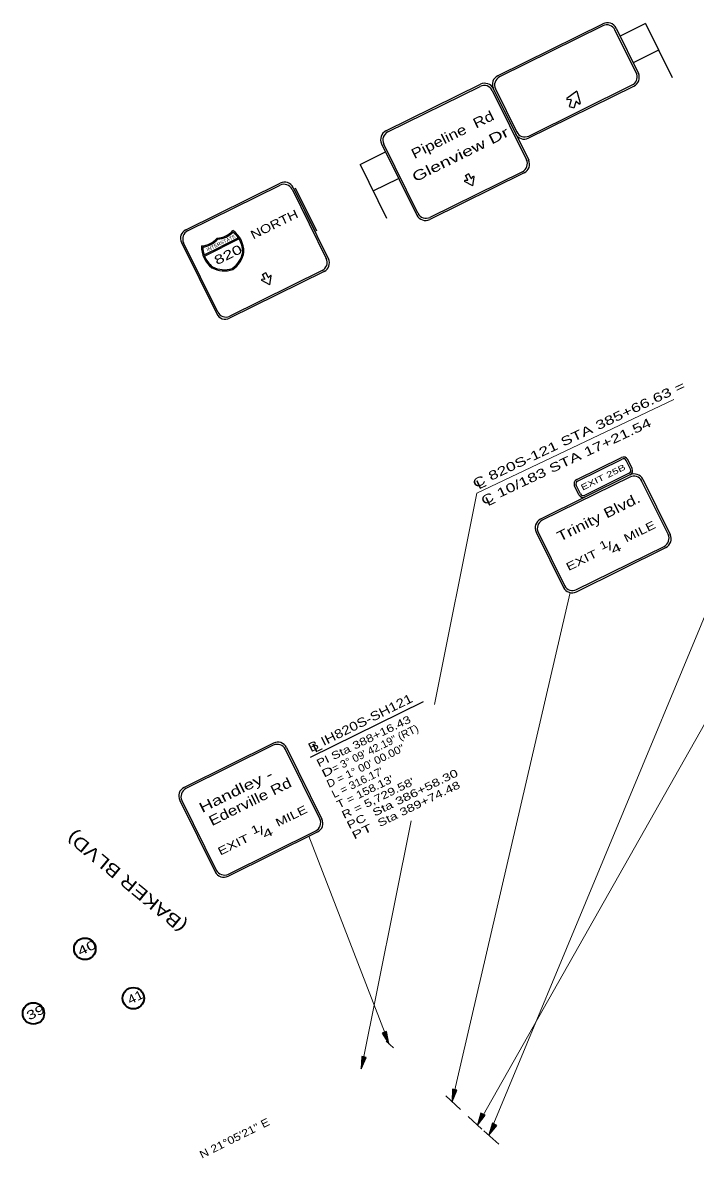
# Model space of a CAD drawing. Extents: x 2356431 to 2371438, y 6972864 to 6982525.
# Drawn here: x 2365913 to 2366966, y 6980043 to 6981822 of the extents above; entities that cross this region are included whole.
import ezdxf
from ezdxf.enums import TextEntityAlignment as Align

# ---------------------------------------------------------------- set-up
doc = ezdxf.new("R2010")
doc.units = 0
doc.header["$LTSCALE"] = 5.6
for name, color, linetype, lineweight in [('1', 7, 'Continuous', 25), ('13', 7, 'Continuous', 13), ('17', 7, 'Continuous', 35), ('28', 7, 'Continuous', 35), ('48', 7, 'Continuous', 25), ('61', 7, 'Continuous', 13)]:
    doc.layers.add(name, color=color, linetype=linetype, lineweight=lineweight)
doc.layers.add('25', color=7, linetype='Continuous')
doc.layers.add('33', color=7, linetype='Continuous')

msp = doc.modelspace()

# ---------------------------------------------------------------- hatches: boundary and pattern name
at = {"layer": '1'}
for points in [[(2366486.56, 6980222.747), (2366482.79, 6980241.916), (2366476.099, 6980239.246)], [(2366585.711, 6980131.985), (2366593.167, 6980150.043), (2366586.115, 6980151.517)], [(2366625.507, 6980094.921), (2366637.074, 6980110.661), (2366630.583, 6980113.784)], [(2366643.099, 6980079.535), (2366655.343, 6980094.757), (2366648.996, 6980098.16)]]:
    msp.add_hatch(color=256, dxfattribs=at).paths.add_polyline_path(points)
at = {"layer": '48'}
msp.add_hatch(color=256, dxfattribs=at).paths.add_polyline_path([(2366443.028, 6980183.363), (2366450.955, 6980201.225), (2366443.947, 6980202.876)])

# ---------------------------------------------------------------- linework, layer by layer
at = {"layer": '1'}
for p, q in [((2366822.168, 6981820.871), (2366656.942, 6981739.325)), ((2366821.727, 6981817.511), (2366659.872, 6981737.639)), ((2366888.321, 6981821.061), (2366848.562, 6981801.372)), ((2366888.321, 6981821.061), (2366930.054, 6981736.797)), ((2366874.917, 6981741.577), (2366840.613, 6981811.099)), ((2366842.31, 6981814.041), (2366877.397, 6981742.946)), ((2366908.913, 6981779.484), (2366869.153, 6981759.794)), ((2366481.942, 6981652.907), (2366630.021, 6981725.98)), ((2366484.869, 6981651.214), (2366629.585, 6981722.627)), ((2366648.42, 6981716.248), (2366701.973, 6981607.725)), ((2366650.101, 6981719.175), (2366705.488, 6981606.941)), ((2366650.101, 6981719.175), (2366684.907, 6981648.642)), ((2366653.469, 6981718.733), (2366686.91, 6981650.971)), ((2366704.924, 6981641.421), (2366870.141, 6981722.966)), ((2366705.635, 6981644.919), (2366867.652, 6981724.878)), ((2366780.897, 6981714.988), (2366765.399, 6981703.698)), ((2366780.897, 6981714.988), (2366786.306, 6981696.607)), ((2366771.515, 6981701.957), (2366765.978, 6981701.831)), ((2366772.181, 6981701.053), (2366768.834, 6981691.215)), ((2366779.329, 6981698.625), (2366775.995, 6981688.797)), ((2366780.379, 6981698.947), (2366784.722, 6981695.486)), ((2366768.834, 6981691.215), (2366772.414, 6981690.006)), ((2366775.995, 6981688.797), (2366772.414, 6981690.006)), ((2366475.143, 6981632.812), (2366530.353, 6981520.922)), ((2366532.043, 6981523.846), (2366478.48, 6981632.381)), ((2366441.311, 6981600.432), (2366481.125, 6981620.012)), ((2366441.311, 6981600.432), (2366482.812, 6981516.051)), ((2366698.515, 6981587.205), (2366550.438, 6981514.12)), ((2366695.596, 6981588.891), (2366550.879, 6981517.469)), ((2366168.323, 6981498.126), (2366316.402, 6981571.199)), ((2366461.788, 6981558.797), (2366501.602, 6981578.38)), ((2366617.788, 6981566.663), (2366605.165, 6981573.536)), ((2366609.552, 6981575.437), (2366605.418, 6981574.966)), ((2366606.491, 6981583.139), (2366609.031, 6981584.39)), ((2366609.941, 6981576.158), (2366606.491, 6981583.139)), ((2366611.579, 6981585.637), (2366609.031, 6981584.39)), ((2366615.033, 6981578.666), (2366611.579, 6981585.637)), ((2366615.859, 6981578.54), (2366618.718, 6981581.531)), ((2366617.788, 6981566.663), (2366620.002, 6981580.859)), ((2366171.25, 6981496.433), (2366315.966, 6981567.846)), ((2366334.801, 6981561.467), (2366388.354, 6981452.944)), ((2366336.482, 6981564.394), (2366391.869, 6981452.16)), ((2366336.482, 6981564.394), (2366371.288, 6981493.861)), ((2366339.85, 6981563.952), (2366373.291, 6981496.19)), ((2366250.828, 6981485.234), (2366223.926, 6981471.955)), ((2366251.833, 6981483.619), (2366224.765, 6981470.261)), ((2366161.524, 6981478.031), (2366216.734, 6981366.141)), ((2366218.424, 6981369.065), (2366164.861, 6981477.6)), ((2366197.025, 6981458.676), (2366223.926, 6981471.955)), ((2366197.678, 6981456.886), (2366224.765, 6981470.261)), ((2366384.896, 6981432.424), (2366236.819, 6981359.339)), ((2366381.977, 6981434.11), (2366237.26, 6981362.688)), ((2366288.637, 6981428.077), (2366291.178, 6981429.327)), ((2366292.09, 6981421.095), (2366288.637, 6981428.077)), ((2366293.727, 6981430.573), (2366291.178, 6981429.327)), ((2366297.169, 6981423.604), (2366293.727, 6981430.573)), ((2366298.007, 6981423.476), (2366300.864, 6981426.469)), ((2366299.936, 6981411.6), (2366287.314, 6981418.472)), ((2366291.698, 6981420.372), (2366287.566, 6981419.904)), ((2366299.936, 6981411.6), (2366302.148, 6981425.795)), ((2366780.736, 6981106.707), (2366850.694, 6981141.223)), ((2366781.977, 6981104.188), (2366851.934, 6981138.702)), ((2366865.047, 6981122.708), (2366858.211, 6981136.568)), ((2366867.574, 6981123.955), (2366860.735, 6981137.815)), ((2366864.163, 6981113.909), (2366723.896, 6981044.48)), ((2366863.709, 6981110.545), (2366726.824, 6981042.802)), ((2366862.919, 6981116.429), (2366792.96, 6981081.927)), ((2366884.144, 6981107.446), (2366927.225, 6981020.407)), ((2366784.155, 6981082.81), (2366777.328, 6981096.667)), ((2366786.681, 6981084.056), (2366779.849, 6981097.91)), ((2366923.849, 6981020.829), (2366882.32, 6981104.747)), ((2366717.07, 6981024.329), (2366759.979, 6980937.627)), ((2366720.259, 6981024.279), (2366761.686, 6980940.569)), ((2366780.155, 6980930.814), (2366920.406, 6981000.227)), ((2366780.592, 6980934.161), (2366917.477, 6981001.915)), ((2366305.896, 6980693.654), (2366165.643, 6980624.195)), ((2366305.442, 6980690.29), (2366168.571, 6980622.518)), ((2366378.212, 6980575.115), (2366324.351, 6980683.896)), ((2366326.046, 6980686.85), (2366381.588, 6980574.694)), ((2366158.818, 6980604.046), (2366214.36, 6980491.879)), ((2366162.204, 6980603.601), (2366216.065, 6980494.822)), ((2366234.537, 6980485.069), (2366374.773, 6980554.512)), ((2366234.973, 6980488.417), (2366371.844, 6980556.2)), ((2366482.452, 6980226.73), (2366493.454, 6980216.486)), ((2366575.79, 6980141.157), (2366598.644, 6980119.878)), ((2366610.421, 6980108.44), (2366632.28, 6980088.89)), ((2366635.408, 6980086.095), (2366658.536, 6980065.41))]:
    msp.add_line(p, q, dxfattribs=at)
at = {"layer": '1', "lineweight": 13}
for p, q in [((2366625.507, 6980094.921), (2367178.928, 6981074.442)), ((2366643.099, 6980079.535), (2367052.364, 6981064.006)), ((2366585.855, 6980132.536), (2366770.595, 6980929.838)), ((2366486.672, 6980222.381), (2366361.108, 6980547.745))]:
    msp.add_line(p, q, dxfattribs=at)
at = {"layer": '1'}
for points in [[(2366486.56, 6980222.747), (2366482.79, 6980241.916), (2366476.099, 6980239.246)], [(2366585.711, 6980131.985), (2366593.167, 6980150.043), (2366586.115, 6980151.517)], [(2366625.507, 6980094.921), (2366637.074, 6980110.661), (2366630.583, 6980113.784)], [(2366643.099, 6980079.535), (2366655.343, 6980094.757), (2366648.996, 6980098.16)]]:
    msp.add_lwpolyline(points, close=True, dxfattribs=at)
for centre, radius, start, end in [((2366827.969, 6981804.859), 14.108, 26.26806, 116.26806), ((2366828.823, 6981807.378), 15.049, 26.26806, 117.68557), ((2366663.603, 6981725.834), 15.049, 116.26806, 206.26806), ((2366666.122, 6981724.98), 14.108, 116.26806, 206.26806), ((2366861.406, 6981737.532), 14.108, 296.26806, 16.67271), ((2366863.757, 6981736.595), 15.049, 295.0985, 24.9686), ((2366635.808, 6981710.021), 14.063, 26.26895, 116.26895), ((2366636.66, 6981712.532), 15.001, 26.26895, 116.26895), ((2366765.972, 6981702.857), 1.012, 126.00656, 271.3877), ((2366771.535, 6981701.297), 0.675, 341.26806, 91.25117), ((2366779.973, 6981698.435), 0.675, 51.28496, 161.26806), ((2366785.337, 6981696.29), 1.012, 231.14843, 16.52957), ((2366488.582, 6981639.453), 15.001, 116.26895, 206.26895), ((2366491.093, 6981638.602), 14.063, 116.26895, 206.26895), ((2366698.537, 6981655.05), 15.049, 206.26806, 295.0985), ((2366699.391, 6981657.57), 14.108, 206.26806, 296.26806), ((2366689.369, 6981601.501), 14.063, 296.26895, 26.26895), ((2366691.88, 6981600.649), 15.001, 296.26895, 26.26895), ((2366322.189, 6981555.24), 14.063, 26.26895, 116.26895), ((2366323.041, 6981557.751), 15.001, 26.26895, 116.26895), ((2366605.513, 6981574.212), 0.759, 96.14753, 241.52867), ((2366609.496, 6981575.919), 0.506, 276.28406, 26.26716), ((2366615.488, 6981578.877), 0.506, 206.26716, 316.25027), ((2366619.266, 6981580.999), 0.759, 351.00566, 136.3868), ((2366543.802, 6981527.57), 15.001, 206.26895, 296.26895), ((2366544.654, 6981530.082), 14.063, 206.26895, 296.26895), ((2366174.963, 6981484.672), 15.001, 116.26895, 206.26895), ((2366177.474, 6981483.82), 14.063, 116.26895, 206.26895), ((2366190.306, 6981508.523), 35.984, 274.23736, 319.08768), ((2366190.306, 6981508.523), 37.874, 276.89292, 317.88976), ((2366215.335, 6981520.876), 35.984, 273.44845, 318.29876), ((2366215.335, 6981520.876), 37.874, 274.64636, 315.6432), ((2366217.443, 6981463.068), 41.954, 0.13125, 53.83362), ((2366217.443, 6981463.068), 40.064, 33.57769, 51.44245), ((2366217.443, 6981463.068), 40.064, 0.34779, 30.85977), ((2366234.908, 6981471.687), 41.954, 178.7025, 232.40488), ((2366234.908, 6981471.687), 40.064, 181.09368, 198.95843), ((2366219.203, 6981469.547), 38.808, 304.1061, 350.75248), ((2366219.203, 6981469.547), 40.698, 303.73996, 350.97586), ((2366234.908, 6981471.687), 40.064, 201.67636, 232.18834), ((2366375.75, 6981446.72), 14.063, 296.26895, 26.26895), ((2366378.261, 6981445.868), 15.001, 296.26895, 26.26895), ((2366228.695, 6981474.232), 40.698, 241.56027, 288.79617), ((2366228.695, 6981474.232), 38.808, 241.78364, 288.43003), ((2366301.411, 6981425.937), 0.759, 351.00566, 136.3868), ((2366287.658, 6981419.15), 0.759, 96.14753, 241.52867), ((2366291.641, 6981420.856), 0.506, 276.28406, 26.26716), ((2366297.634, 6981423.814), 0.506, 206.26716, 316.25027), ((2366230.184, 6981372.789), 15.001, 206.26895, 296.26895), ((2366231.035, 6981375.3), 14.063, 206.26895, 296.26895), ((2366854.01, 6981134.493), 7.501, 26.25603, 116.25603), ((2366854.01, 6981134.493), 4.688, 26.25603, 116.25603), ((2366860.846, 6981120.636), 7.501, 296.25603, 26.25603), ((2366784.051, 6981099.984), 7.501, 116.25603, 206.25603), ((2366860.846, 6981120.636), 4.688, 296.25603, 26.25603), ((2366869.983, 6981097.903), 14.108, 26.33129, 116.33129), ((2366870.834, 6981100.424), 15.049, 26.33129, 116.33129), ((2366784.051, 6981099.984), 4.688, 116.25603, 206.25603), ((2366790.887, 6981086.127), 7.501, 206.25603, 296.25603), ((2366790.887, 6981086.127), 4.688, 206.25603, 296.25603), ((2366730.567, 6981031.004), 15.049, 116.33129, 206.33129), ((2366733.087, 6981030.152), 14.108, 116.33129, 206.33129), ((2366911.227, 6981014.568), 14.108, 296.33129, 26.33129), ((2366913.747, 6981013.717), 15.049, 296.33129, 26.33129), ((2366773.479, 6980944.297), 15.049, 206.33129, 296.33129), ((2366774.331, 6980946.817), 14.108, 206.33129, 296.33129), ((2366311.717, 6980677.649), 14.108, 26.34329, 116.34329), ((2366312.568, 6980680.17), 15.049, 26.34329, 116.34329), ((2366172.315, 6980610.721), 15.049, 116.34329, 206.34329), ((2366174.835, 6980609.87), 14.108, 116.34329, 206.34329), ((2366365.591, 6980568.852), 14.108, 296.34329, 26.34329), ((2366368.111, 6980568.001), 15.049, 296.34329, 26.34329), ((2366227.858, 6980498.552), 15.049, 206.34329, 296.34329), ((2366228.709, 6980501.072), 14.108, 206.34329, 296.34329)]:
    msp.add_arc(centre, radius, start, end, dxfattribs=at)
at = {"layer": '17'}
for centre in [(2366010.198, 6980371.396), (2366086.12, 6980294.054), (2365929.685, 6980270.182)]:
    msp.add_circle(centre, 16.828, dxfattribs=at)
at = {"layer": '48', "lineweight": 13}
for p, q in [((2366932.867, 6981231.912), (2366624.47, 6981085.098)), ((2366558.055, 6980754.468), (2366624.47, 6981085.098)), ((2366443.57, 6980184.532), (2366521.377, 6980571.877))]:
    msp.add_line(p, q, dxfattribs=at)
at = {"layer": '48'}
msp.add_lwpolyline([(2366443.028, 6980183.363), (2366450.955, 6980201.225), (2366443.947, 6980202.876)], close=True, dxfattribs=at)
at = {"layer": '61', "lineweight": 25}
msp.add_line((2366363.668, 6980671.446), (2366540.625, 6980758.781), dxfattribs=at)

# ---------------------------------------------------------------- texts
at = {"layer": '1'}
for s, height, rotation, width, p in [('Pipeline  Rd', 15.68, 26.268, 1.25, (2366589.663, 6981639.973)), ('Glenview Dr', 15.68, 26.268, 1.45, (2366602.001, 6981608.947)), ('NORTH', 13.5, 26.269, 1.25, (2366309.914, 6981500.48)), ('EXIT 25B', 9.188, 26.256, 1.45, (2366824.089, 6981106.148)), ('Trinity Blvd.', 15.68, 26.331, 1.3, (2366818.189, 6981040.644)), ('MILE', 12.54, 26.331, 1.35, (2366882.023, 6981019.66)), ('1', 12.54, 26.331, 1.3, (2366825.378, 6980998.741)), ('/', 12.54, 26.331, 1.7, (2366835.6, 6980996.681)), ('4', 12.54, 26.331, 1.75, (2366845.084, 6980992.953)), ('EXIT', 12.54, 26.331, 1.4, (2366791.238, 6980974.726)), ('Handley -', 15.68, 26.343, 1.4, (2366250.232, 6980611.949)), ('Ederville Rd', 15.68, 26.343, 1.25, (2366272.551, 6980594.907)), ('MILE', 12.54, 26.343, 1.35, (2366336.388, 6980573.938)), ('1', 12.54, 26.343, 1.3, (2366279.748, 6980553.006)), ('/', 12.54, 26.343, 1.7, (2366289.971, 6980550.948)), ('4', 12.54, 26.343, 1.75, (2366299.456, 6980547.221)), ('EXIT', 12.54, 26.343, 1.4, (2366245.613, 6980528.984))]:
    msp.add_text(s, height=height, rotation=rotation, dxfattribs=dict(at, width=width)).set_placement(p, align=Align.CENTER)
for s, height, width, p in [('INTERSTATE', 5.198, 1.15, (2366202.338, 6981464.001)), ('820', 14.18, 1.45, (2366217.134, 6981442.464))]:
    msp.add_text(s, height=height, rotation=26.268, dxfattribs=dict(at, width=width)).set_placement(p)
at = {"layer": '13', "width": 1.25}
msp.add_text('(BAKER BLVD)', height=20, rotation=140.54, dxfattribs=at).set_placement((2366171.689, 6980410.465))
at = {"layer": '17'}
for s, width, p in [('40', 1.45, (2366016.443, 6980366.671)), ('41', 1.2, (2366092.366, 6980289.33)), ('39', 1.4, (2365935.981, 6980265.482))]:
    msp.add_text(s, height=14, rotation=26.268, dxfattribs=dict(at, width=width)).set_placement(p, align=Align.CENTER)
at = {"layer": '25'}
for s, width, p in [('C 820S-121 STA 385+66.63 =', 1.45, (2366621.838, 6981093.006)), ('C 10/183 STA 17+21.54', 1.45, (2366635.045, 6981066.24)), ('L', 1.4, (2366627.163, 6981090.934)), ('L', 1.4, (2366641.599, 6981064.605))]:
    msp.add_text(s, height=14, rotation=25.268, dxfattribs=dict(at, width=width)).set_placement(p)
at = {"layer": '28'}
for s, height, rotation, width, p in [('B IH820S-SH121 ', 14, 26.377, 1.25, (2366447.717, 6980720.521)), ('N 21°05\'21" E', 12, 26.524, 1.2, (2366247.249, 6980069.287))]:
    msp.add_text(s, height=height, rotation=rotation, dxfattribs=dict(at, width=width)).set_placement(p, align=Align.CENTER)
at = {"layer": '33'}
for s, width, p in [('PI Sta 388+16.43', 1.3, (2366376.841, 6980655.826)), ('= 3° 09\' 42.19" (RT)', 1.05, (2366400.909, 6980647.558)), ('D = 1° 00\' 00.00"', 1.1, (2366392.627, 6980623.495)), ('D', 1.55, (2366384.735, 6980639.66)), ("L = 316.17'", 1.1, (2366400.52, 6980607.329)), ("T = 158.13'", 1.2, (2366408.414, 6980591.163)), ('Sta 386+58.30', 1.4, (2366464.323, 6980578.455)), ("R = 5,729.58'", 1.3, (2366416.307, 6980574.997)), ('Sta 389+74.48', 1.35, (2366472.339, 6980562.038)), ('PC', 1.4, (2366424.2, 6980558.831)), ('PT', 1.6, (2366432.093, 6980542.665))]:
    msp.add_text(s, height=12, rotation=26.024, dxfattribs=dict(at, width=width)).set_placement(p)
at = {"layer": '61', "width": 1.4}
msp.add_text('L', height=14, rotation=26.268, dxfattribs=at).set_placement((2366377.161, 6980681.551), align=Align.CENTER)

doc.saveas('drawing.dxf')
